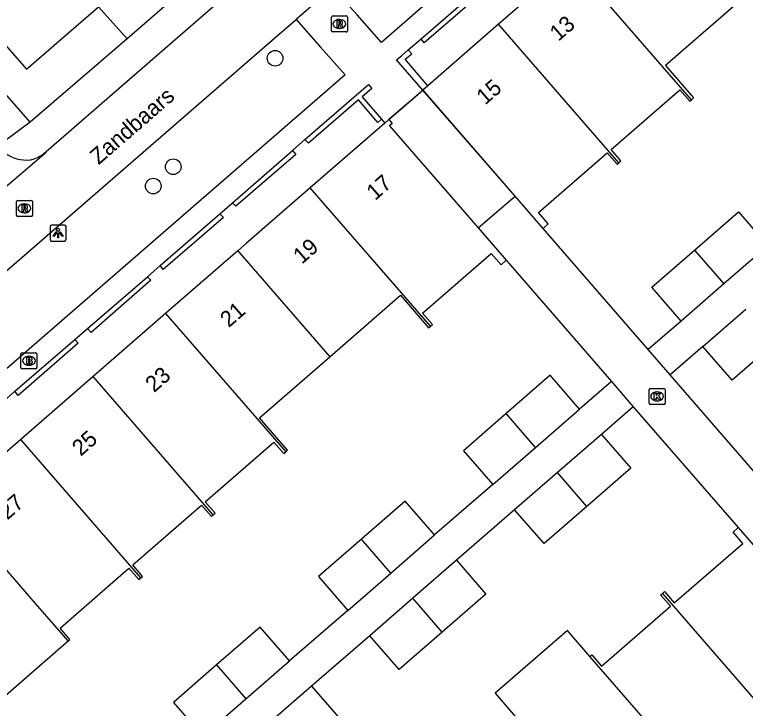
# Model space of a CAD drawing. Extents: x 155888 to 156864, y 383882 to 384671.
# Drawn here: x 156692.46 to 156738.11, y 384260.74 to 384304.09 of the extents above; entities that cross this region are included whole.
import ezdxf

# ---------------------------------------------------------------- set-up
doc = ezdxf.new("R2010")
doc.units = 0
for name, color, linetype in [('IMGEO_Boom', 7, 'Continuous'), ('IMGEO_Brandkraan', 7, 'Continuous'), ('IMGEO_Kolk', 7, 'Continuous'), ('IMGEO_Lichtpunt', 7, 'Continuous'), ('IMGEO_Muur', 7, 'Continuous'), ('IMGEO_Openbare_ruimte_label', 7, 'Continuous'), ('IMGEO_Pand', 7, 'Continuous'), ('IMGEO_Pand_nummerreeks', 7, 'Continuous'), ('IMGEO_Pand_overbouw', 7, 'Continuous'), ('IMGEO_Rijbaan_lokaal_gesloten', 7, 'Continuous'), ('IMGEO_Rioolput', 7, 'Continuous'), ('IMGEO_Voetpad_open', 7, 'Continuous')]:
    doc.layers.add(name, color=color, linetype=linetype)

msp = doc.modelspace()

# ---------------------------------------------------------------- linework, layer by layer
at = {"layer": 'IMGEO_Boom'}
for centre in [(156708.732, 384301.362), (156702.366, 384294.582), (156701.117, 384293.377)]:
    msp.add_circle(centre, 0.489, dxfattribs=at)
at = {"layer": 'IMGEO_Brandkraan'}
for p, q in [((156692.851, 384282.036), (156692.851, 384282.888)), ((156692.926, 384282.962), (156693.778, 384282.962)), ((156693.852, 384282.888), (156693.852, 384282.036)), ((156693.339, 384282.742), (156693.364, 384282.742)), ((156693.778, 384281.962), (156692.926, 384281.962)), ((156693.362, 384282.182), (156693.337, 384282.182))]:
    msp.add_line(p, q, dxfattribs=at)
for points in [[(156692.851, 384282.036), (156692.851, 384282.888)], [(156692.926, 384282.962), (156693.778, 384282.962)], [(156693.852, 384282.888), (156693.852, 384282.036)], [(156693.199, 384282.662), (156693.199, 384282.262), (156693.412, 384282.262)], [(156693.43, 384282.662), (156693.199, 384282.662)], [(156693.378, 384282.581), (156693.324, 384282.581), (156693.324, 384282.505)], [(156693.324, 384282.505), (156693.377, 384282.505)], [(156693.386, 384282.429), (156693.324, 384282.429), (156693.324, 384282.348)], [(156693.324, 384282.348), (156693.386, 384282.348)], [(156693.778, 384281.962), (156692.926, 384281.962)]]:
    msp.add_lwpolyline(points, dxfattribs=at)
for centre, radius, start, end in [((156692.928, 384282.886), 0.0765, 91.552, 178.448), ((156692.928, 384282.886), 0.0765, 91.552, 178.448), ((156693.776, 384282.886), 0.0765, 1.552, 88.448), ((156693.776, 384282.886), 0.0765, 1.552, 88.448), ((156693.379, 384282.543), 0.0379, 267.8285, 90.9355), ((156693.387, 384282.388), 0.0404, 269.8759, 90.5077), ((156693.434, 384282.517), 0.145, 59.4692, 91.5367), ((156693.459, 384282.564), 0.0922, 285.5137, 58.1501), ((156693.464, 384282.372), 0.105, 301.3115, 78.989), ((156692.928, 384282.038), 0.0765, 181.552, 268.448), ((156692.928, 384282.038), 0.0765, 181.552, 268.448), ((156693.418, 384282.513), 0.251, 268.6676, 293.5347), ((156693.776, 384282.038), 0.0765, 271.552, 358.448), ((156693.776, 384282.038), 0.0765, 271.552, 358.448)]:
    msp.add_arc(centre, radius, start, end, dxfattribs=at)
for centre, major_axis, ratio, start_param, end_param in [((156693.338, 384282.462), (-0.387, 0.002), 0.722429, 4.712389, 7.853982), ((156693.363, 384282.462), (-0.39, 0.002), 0.717154, 1.570796, 4.712389)]:
    msp.add_ellipse(centre, major_axis=major_axis, ratio=ratio, start_param=start_param, end_param=end_param, dxfattribs=at)
at = {"layer": 'IMGEO_Kolk'}
for p, q in [((156732.097, 384279.808), (156732.097, 384280.66)), ((156732.172, 384280.734), (156733.024, 384280.734)), ((156732.585, 384280.514), (156732.61, 384280.514)), ((156733.098, 384280.66), (156733.098, 384279.808)), ((156733.024, 384279.734), (156732.172, 384279.734)), ((156732.608, 384279.954), (156732.583, 384279.954))]:
    msp.add_line(p, q, dxfattribs=at)
for points in [[(156732.097, 384279.808), (156732.097, 384280.66)], [(156732.172, 384280.734), (156733.024, 384280.734)], [(156733.098, 384280.66), (156733.098, 384279.808)], [(156732.418, 384280.434), (156732.541, 384280.434), (156732.541, 384280.283), (156732.671, 384280.434), (156732.835, 384280.434), (156732.689, 384280.283), (156732.842, 384280.034), (156732.69, 384280.034), (156732.605, 384280.198), (156732.541, 384280.131), (156732.541, 384280.034), (156732.418, 384280.034), (156732.418, 384280.434)], [(156733.024, 384279.734), (156732.172, 384279.734)]]:
    msp.add_lwpolyline(points, dxfattribs=at)
for centre, start, end in [((156732.174, 384280.658), 91.552, 178.448), ((156732.174, 384280.658), 91.552, 178.448), ((156733.022, 384280.658), 1.552, 88.448), ((156733.022, 384280.658), 1.552, 88.448), ((156732.174, 384279.81), 181.552, 268.448), ((156732.174, 384279.81), 181.552, 268.448), ((156733.022, 384279.81), 271.552, 358.448), ((156733.022, 384279.81), 271.552, 358.448)]:
    msp.add_arc(centre, 0.0765, start, end, dxfattribs=at)
for centre, major_axis, ratio, start_param, end_param in [((156732.584, 384280.234), (-0.387, 0.002), 0.722429, 4.712389, 7.853982), ((156732.609, 384280.234), (-0.39, 0.002), 0.717154, 1.570796, 4.712389)]:
    msp.add_ellipse(centre, major_axis=major_axis, ratio=ratio, start_param=start_param, end_param=end_param, dxfattribs=at)
at = {"layer": 'IMGEO_Lichtpunt'}
for p, q in [((156694.671, 384290.844), (156694.671, 384290.037)), ((156694.671, 384290.844), (156694.671, 384290.037)), ((156695.573, 384290.939), (156694.765, 384290.939)), ((156695.573, 384290.939), (156694.765, 384290.939)), ((156695.667, 384290.037), (156695.667, 384290.844)), ((156695.667, 384290.037), (156695.667, 384290.844)), ((156694.765, 384289.943), (156695.573, 384289.943)), ((156694.765, 384289.943), (156695.573, 384289.943))]:
    msp.add_line(p, q, dxfattribs=at)
for points in [[(156695.045, 384290.508), (156695.084, 384290.48), (156694.896, 384290.218), (156694.858, 384290.245), (156695.045, 384290.508)], [(156695.147, 384290.46), (156695.194, 384290.46), (156695.194, 384290.138), (156695.147, 384290.138), (156695.147, 384290.46)], [(156695.257, 384290.48), (156695.295, 384290.507), (156695.482, 384290.245), (156695.443, 384290.217), (156695.257, 384290.48)]]:
    msp.add_lwpolyline(points, dxfattribs=at)
msp.add_circle((156695.17, 384290.642), 0.0994, dxfattribs=at)
for centre, start, end in [((156694.765, 384290.844), 90, 180), ((156694.765, 384290.844), 90, 180), ((156695.573, 384290.844), 0, 90), ((156695.573, 384290.844), 0, 90), ((156694.765, 384290.037), 180, 270), ((156694.765, 384290.037), 180, 270), ((156695.573, 384290.037), 270, 0), ((156695.573, 384290.037), 270, 360)]:
    msp.add_arc(centre, 0.0946, start, end, dxfattribs=at)
at = {"layer": 'IMGEO_Muur'}
for points in [[(156709.961, 384311.676), (156699.483, 384302.567)], [(156721.567, 384305.808), (156721.784, 384305.572), (156718.054, 384302.333), (156717.849, 384302.58)], [(156717.849, 384302.58), (156721.567, 384305.808)], [(156699.483, 384302.567), (156697.695, 384304.581)], [(156717.965, 384299.373), (156716.321, 384301.263), (156716.648, 384301.537), (156717.047, 384301.892)], [(156718.274, 384299.641), (156716.852, 384301.3), (156717.273, 384301.638), (156717.047, 384301.892)], [(156710.597, 384296.288), (156714.566, 384299.721), (156714.773, 384299.481), (156714.172, 384298.955), (156715.385, 384297.561)], [(156715.385, 384297.561), (156715.148, 384297.351), (156713.933, 384298.756), (156710.809, 384296.048), (156710.597, 384296.288)], [(156709.822, 384295.594), (156710.034, 384295.359), (156706.279, 384292.115), (156706.068, 384292.337)], [(156706.068, 384292.337), (156709.822, 384295.594)], [(156705.276, 384291.651), (156705.505, 384291.418), (156701.741, 384288.167), (156701.539, 384288.407)], [(156701.539, 384288.407), (156705.276, 384291.651)], [(156700.759, 384287.709), (156700.957, 384287.489), (156697.242, 384284.227), (156697.004, 384284.474)], [(156697.004, 384284.474), (156700.759, 384287.709)], [(156696.219, 384283.796), (156696.429, 384283.556), (156692.678, 384280.293), (156692.463, 384280.556)], [(156692.463, 384280.556), (156696.219, 384283.796)]]:
    msp.add_lwpolyline(points, dxfattribs=at)
at = {"layer": 'IMGEO_Pand'}
for points in [[(156691.016, 384311.093), (156693.131, 384308.665), (156689.211, 384305.218), (156693.203, 384300.685), (156697.695, 384304.581), (156700.384, 384306.913), (156696.628, 384311.229), (156699.268, 384313.525), (156696.916, 384316.228)], [(156727.226, 384307.418), (156722.699, 384303.485)], [(156734.741, 384298.765), (156727.226, 384307.418)], [(156737.518, 384304.718), (156733.123, 384300.907), (156734.877, 384298.883), (156734.741, 384298.765)], [(156722.699, 384303.485), (156718.274, 384299.641)], [(156730.208, 384294.834), (156722.699, 384303.485)], [(156718.274, 384299.641), (156717.965, 384299.373)], [(156725.48, 384290.734), (156723.724, 384292.753), (156717.965, 384299.373)], [(156730.208, 384294.834), (156730.338, 384294.947), (156729.722, 384295.656), (156734.025, 384299.388), (156734.642, 384298.679), (156734.741, 384298.765)], [(156715.582, 384297.306), (156715.843, 384297.533)], [(156715.843, 384297.533), (156716.052, 384297.294), (156715.886, 384297.149), (156721.422, 384290.758), (156723.171, 384288.738)], [(156715.582, 384297.306), (156710.924, 384293.262)], [(156725.48, 384290.734), (156725.798, 384291.01), (156725.183, 384291.719), (156729.486, 384295.452), (156730.102, 384294.742), (156730.208, 384294.834)], [(156710.924, 384293.262), (156706.94, 384289.802), (156706.396, 384289.33)], [(156718.43, 384284.617), (156710.924, 384293.262)], [(156734.942, 384289.38), (156737.681, 384291.758), (156739.516, 384289.645)], [(156739.516, 384289.645), (156736.777, 384287.266)], [(156706.396, 384289.33), (156701.884, 384285.409)], [(156706.396, 384289.33), (156712.141, 384282.713)], [(156734.104, 384284.945), (156732.269, 384287.059), (156734.942, 384289.38)], [(156734.942, 384289.38), (156736.777, 384287.266)], [(156718.43, 384284.617), (156718.555, 384284.726), (156717.938, 384285.435), (156722.23, 384289.164), (156722.847, 384288.456), (156723.171, 384288.738)], [(156736.777, 384287.266), (156734.104, 384284.945)], [(156712.141, 384282.713), (156716.556, 384286.55), (156718.32, 384284.522), (156718.43, 384284.617)], [(156735.459, 384283.361), (156738.143, 384285.692)], [(156701.884, 384285.409), (156697.363, 384281.482)], [(156701.884, 384285.409), (156709.391, 384276.763)], [(156739.978, 384283.578), (156737.294, 384281.247), (156735.459, 384283.361)], [(156709.391, 384276.763), (156709.51, 384276.867), (156707.748, 384278.895), (156712.141, 384282.713)], [(156697.363, 384281.482), (156692.836, 384277.549)], [(156704.871, 384272.835), (156697.363, 384281.482)], [(156727.754, 384279.442), (156725.919, 384281.556), (156723.165, 384279.164)], [(156723.165, 384279.164), (156720.492, 384276.843), (156722.327, 384274.73)], [(156725, 384277.05), (156723.165, 384279.164)], [(156725, 384277.05), (156727.754, 384279.442)], [(156729.126, 384277.861), (156726.373, 384275.47)], [(156729.126, 384277.861), (156730.961, 384275.748), (156728.208, 384273.357)], [(156692.836, 384277.549), (156688.294, 384273.603)], [(156700.345, 384268.902), (156692.836, 384277.549)], [(156704.871, 384272.835), (156704.984, 384272.933), (156704.368, 384273.642), (156708.659, 384277.371), (156709.275, 384276.662), (156709.391, 384276.763)], [(156722.327, 384274.73), (156725, 384277.05)], [(156726.373, 384275.47), (156723.699, 384273.149)], [(156728.208, 384273.357), (156726.373, 384275.47)], [(156718.697, 384271.577), (156716.861, 384273.691), (156714.123, 384271.313)], [(156695.803, 384264.954), (156693.895, 384267.152), (156688.294, 384273.603)], [(156700.345, 384268.902), (156700.449, 384268.992), (156699.832, 384269.701), (156704.132, 384273.436), (156704.749, 384272.729), (156704.871, 384272.835)], [(156728.208, 384273.357), (156725.534, 384271.035), (156723.699, 384273.149)], [(156732.926, 384267.924), (156733.054, 384268.035), (156733.67, 384267.327), (156737.96, 384271.048), (156737.345, 384271.759), (156737.663, 384272.034)], [(156737.663, 384272.034), (156739.407, 384270.032), (156744.969, 384263.644), (156745.135, 384263.792), (156745.344, 384263.552)], [(156715.958, 384269.199), (156718.697, 384271.577)], [(156714.123, 384271.313), (156711.434, 384268.978), (156713.269, 384266.865)], [(156715.958, 384269.199), (156714.123, 384271.313)], [(156720.069, 384269.996), (156717.331, 384267.618)], [(156720.069, 384269.996), (156721.904, 384267.882), (156719.166, 384265.505)], [(156695.803, 384264.954), (156695.913, 384265.05), (156695.298, 384265.76), (156699.598, 384269.496), (156700.214, 384268.788), (156700.345, 384268.902)], [(156713.269, 384266.865), (156715.958, 384269.199)], [(156728.395, 384263.993), (156728.513, 384264.095), (156729.129, 384263.386), (156733.434, 384267.122), (156732.819, 384267.831), (156732.926, 384267.924)], [(156732.926, 384267.924), (156740.429, 384259.284)], [(156717.331, 384267.618), (156714.642, 384265.283)], [(156719.166, 384265.505), (156717.331, 384267.618)], [(156709.639, 384263.712), (156707.804, 384265.826), (156705.074, 384263.456)], [(156719.166, 384265.505), (156716.477, 384263.17), (156714.642, 384265.283)], [(156728.395, 384263.993), (156726.996, 384265.606), (156722.481, 384261.689), (156723.88, 384260.076)], [(156691.276, 384261.02), (156691.393, 384261.122), (156695.803, 384264.954)], [(156706.91, 384261.342), (156709.639, 384263.712)], [(156735.899, 384255.351), (156728.395, 384263.993)], [(156705.074, 384263.456), (156702.376, 384261.113), (156704.212, 384259)], [(156705.074, 384263.456), (156706.91, 384261.342)], [(156711.011, 384262.13), (156708.283, 384259.761)], [(156711.011, 384262.13), (156712.846, 384260.017), (156710.118, 384257.647)], [(156704.212, 384259), (156706.91, 384261.342)]]:
    msp.add_lwpolyline(points, dxfattribs=at)
at = {"layer": 'IMGEO_Pand_overbouw'}
msp.add_lwpolyline([(156721.422, 384290.758), (156723.724, 384292.753), (156717.977, 384299.359), (156715.843, 384297.533), (156716.052, 384297.294), (156715.886, 384297.149)], close=True, dxfattribs=at)
at = {"layer": 'IMGEO_Rijbaan_lokaal_gesloten'}
for points in [[(156694.426, 384295.545), (156762.47, 384354.624), (156763.365, 384355.478), (156770.406, 384362.354)], [(156712.324, 384305.79), (156710.042, 384303.791)], [(156673.475, 384272.027), (156674.975, 384273.325), (156691.805, 384287.952), (156708.555, 384302.487), (156710.042, 384303.791)], [(156688.781, 384290.696), (156688.813, 384290.7), (156694.427, 384295.502), (156694.426, 384295.545)]]:
    msp.add_lwpolyline(points, dxfattribs=at)
for centre, radius, start, end in [((156693.098, 384297.096), 2.072, 216.4449, 261.6276), ((156693.183, 384296.692), 1.691, 256.7615, 317.2809)]:
    msp.add_arc(centre, radius, start, end, dxfattribs=at)
at = {"layer": 'IMGEO_Rioolput'}
for p, q in [((156712.248, 384303.077), (156712.248, 384303.929)), ((156712.323, 384304.003), (156713.175, 384304.003)), ((156712.736, 384303.783), (156712.761, 384303.783)), ((156713.249, 384303.929), (156713.249, 384303.077)), ((156713.175, 384303.003), (156712.323, 384303.003)), ((156712.759, 384303.223), (156712.734, 384303.223)), ((156692.566, 384291.558), (156692.566, 384292.41)), ((156692.641, 384292.484), (156693.493, 384292.484)), ((156693.567, 384292.41), (156693.567, 384291.558)), ((156693.054, 384292.264), (156693.079, 384292.264)), ((156693.493, 384291.484), (156692.641, 384291.484)), ((156693.077, 384291.704), (156693.052, 384291.704))]:
    msp.add_line(p, q, dxfattribs=at)
for points in [[(156712.248, 384303.077), (156712.248, 384303.929)], [(156712.323, 384304.003), (156713.175, 384304.003)], [(156713.249, 384303.929), (156713.249, 384303.077)], [(156712.837, 384303.701), (156712.585, 384303.703), (156712.585, 384303.303)], [(156712.585, 384303.303), (156712.709, 384303.303), (156712.709, 384303.465), (156712.72, 384303.465)], [(156712.763, 384303.622), (156712.709, 384303.622), (156712.709, 384303.541)], [(156712.709, 384303.541), (156712.761, 384303.541)], [(156712.767, 384303.436), (156712.838, 384303.303), (156712.978, 384303.303), (156712.913, 384303.429)], [(156713.175, 384303.003), (156712.323, 384303.003)], [(156692.566, 384291.558), (156692.566, 384292.41)], [(156692.641, 384292.484), (156693.493, 384292.484)], [(156693.567, 384292.41), (156693.567, 384291.558)], [(156693.155, 384292.182), (156692.903, 384292.184), (156692.903, 384291.784)], [(156692.903, 384291.784), (156693.027, 384291.784), (156693.027, 384291.946), (156693.038, 384291.946)], [(156693.081, 384292.103), (156693.027, 384292.103), (156693.027, 384292.022)], [(156693.027, 384292.022), (156693.079, 384292.022)], [(156693.085, 384291.917), (156693.156, 384291.784), (156693.296, 384291.784), (156693.231, 384291.91)], [(156693.493, 384291.484), (156692.641, 384291.484)]]:
    msp.add_lwpolyline(points, dxfattribs=at)
for centre, radius, start, end in [((156712.325, 384303.927), 0.0765, 91.552, 178.448), ((156712.325, 384303.927), 0.0765, 91.552, 178.448), ((156713.173, 384303.927), 0.0765, 1.552, 88.448), ((156713.173, 384303.927), 0.0765, 1.552, 88.448), ((156712.719, 384303.412), 0.0533, 26.0293, 88.6989), ((156712.745, 384303.73), 0.19, 274.7715, 282.9687), ((156712.769, 384303.526), 0.0964, 77.0061, 93.1865), ((156712.783, 384303.583), 0.0378, 276.6634, 79.6772), ((156712.836, 384303.591), 0.109, 350.3612, 89.416), ((156712.834, 384303.591), 0.112, 277.5842, 350.9817), ((156712.818, 384303.376), 0.108, 29.5134, 73.7905), ((156712.325, 384303.079), 0.0765, 181.552, 268.448), ((156712.325, 384303.079), 0.0765, 181.552, 268.448), ((156713.173, 384303.079), 0.0765, 271.552, 358.448), ((156713.173, 384303.079), 0.0765, 271.552, 358.448), ((156692.643, 384292.408), 0.0765, 91.552, 178.448), ((156692.643, 384292.408), 0.0765, 91.552, 178.448), ((156693.491, 384292.408), 0.0765, 1.552, 88.448), ((156693.491, 384292.408), 0.0765, 1.552, 88.448), ((156693.037, 384291.893), 0.0533, 26.0293, 88.6989), ((156693.063, 384292.211), 0.19, 274.7715, 282.9687), ((156693.087, 384292.007), 0.0964, 77.0061, 93.1865), ((156693.101, 384292.064), 0.0378, 276.6634, 79.6772), ((156693.154, 384292.072), 0.109, 350.3612, 89.416), ((156693.152, 384292.072), 0.112, 277.5842, 350.9817), ((156693.136, 384291.857), 0.108, 29.5134, 73.7905), ((156692.643, 384291.56), 0.0765, 181.552, 268.448), ((156692.643, 384291.56), 0.0765, 181.552, 268.448), ((156693.491, 384291.56), 0.0765, 271.552, 358.448), ((156693.491, 384291.56), 0.0765, 271.552, 358.448)]:
    msp.add_arc(centre, radius, start, end, dxfattribs=at)
for centre, major_axis, ratio, start_param, end_param in [((156712.735, 384303.503), (-0.387, 0.002), 0.722429, 4.712389, 7.853982), ((156712.76, 384303.503), (-0.39, 0.002), 0.717154, 1.570796, 4.712389), ((156693.053, 384291.984), (-0.387, 0.002), 0.722429, 4.712389, 7.853982), ((156693.078, 384291.984), (-0.39, 0.002), 0.717154, 1.570796, 4.712389)]:
    msp.add_ellipse(centre, major_axis=major_axis, ratio=ratio, start_param=start_param, end_param=end_param, dxfattribs=at)
at = {"layer": 'IMGEO_Voetpad_open'}
for points in [[(156748.988, 384337.664), (156750.444, 384335.978), (156751.947, 384334.237), (156715.384, 384302.356), (156713.856, 384304.071), (156712.324, 384305.79)], [(156709.961, 384311.676), (156699.483, 384302.567), (156693.423, 384297.378)], [(156710.042, 384303.791), (156711.571, 384302.065), (156713.109, 384300.329), (156676.443, 384268.529), (156674.96, 384270.277), (156673.475, 384272.027)], [(156717.047, 384301.892), (156717.849, 384302.58)], [(156693.423, 384297.378), (156691.693, 384299.344)], [(156715.843, 384297.533), (156717.965, 384299.373)], [(156715.385, 384297.561), (156715.582, 384297.306)], [(156693.423, 384297.378), (156691.796, 384296.165)], [(156709.822, 384295.594), (156710.597, 384296.288)], [(156705.276, 384291.651), (156706.068, 384292.337)], [(156732.05, 384283.163), (156725.48, 384290.734)], [(156723.171, 384288.738), (156729.741, 384281.166)], [(156700.759, 384287.709), (156701.539, 384288.407)], [(156734.104, 384284.945), (156732.05, 384283.163)], [(156696.219, 384283.796), (156697.004, 384284.474)], [(156735.459, 384283.361), (156733.416, 384281.588)], [(156733.416, 384281.588), (156732.05, 384283.163)], [(156739.962, 384274.044), (156733.416, 384281.588)], [(156729.741, 384281.166), (156727.754, 384279.442)], [(156729.741, 384281.166), (156731.112, 384279.584)], [(156691.691, 384279.856), (156692.463, 384280.556)], [(156731.112, 384279.584), (156729.126, 384277.861)], [(156731.112, 384279.584), (156737.663, 384272.034)], [(156722.327, 384274.73), (156718.697, 384271.577)], [(156723.699, 384273.149), (156720.069, 384269.996)], [(156713.269, 384266.865), (156709.639, 384263.712)], [(156714.642, 384265.283), (156711.011, 384262.13)]]:
    msp.add_lwpolyline(points, dxfattribs=at)

# ---------------------------------------------------------------- texts
at = {"layer": 'IMGEO_Openbare_ruimte_label'}
msp.add_text('Zandbaars', height=1, rotation=40.9865, dxfattribs=at).set_placement((156697.706, 384294.673))
at = {"layer": 'IMGEO_Pand_nummerreeks'}
for s, rotation, p in [('13', 40.9805, (156726.429, 384302.381)), ('15', 40.9805, (156721.85, 384298.403)), ('17', 40.9799, (156714.983, 384292.441)), ('19', 40.9799, (156710.401, 384288.461)), ('21', 40.9799, (156705.835, 384284.496)), ('23', 40.9799, (156701.168, 384280.441)), ('25', 40.9799, (156696.586, 384276.461)), ('27', 40.9779, (156692.005, 384272.481))]:
    msp.add_text(s, height=1, rotation=rotation, dxfattribs=at).set_placement(p)

doc.saveas('drawing.dxf')
